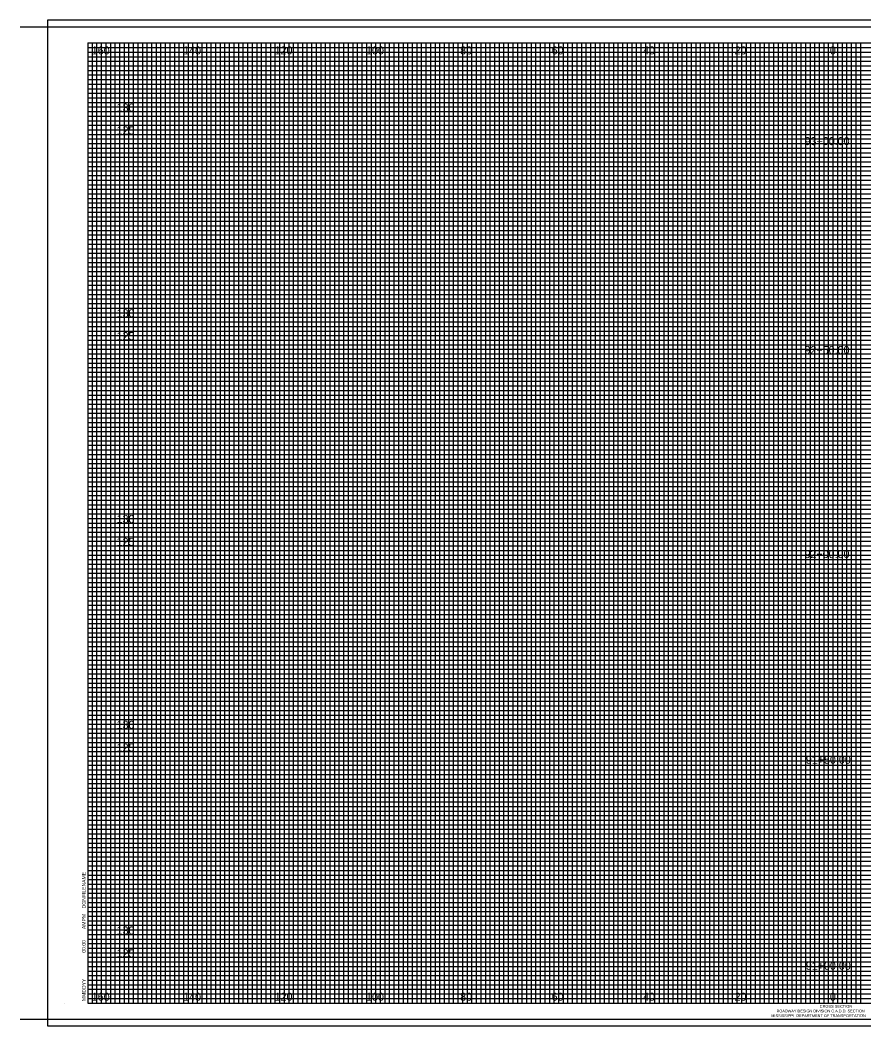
# Model space of a CAD drawing. Extents: x -3604 to 2303, y -13 to 9543.
# Drawn here: x -3604.5 to -3420, y 5764.1 to 5984.1 of the extents above; entities that cross this region are included whole.
import ezdxf

# ---------------------------------------------------------------- set-up
doc = ezdxf.new("R2010")
doc.units = 0
for name, color, linetype in [('SHEET_BORDER', 7, 'Continuous'), ('SHEET_BORDER_TX', 7, 'Continuous'), ('SHEET_DATE_DGN_TX', 7, 'Continuous'), ('SHEET_PLOTTING_SHAPE', 7, 'Continuous'), ('XS_SHEET_LABELS_ELEVATION', 7, 'Continuous'), ('XS_SHEET_LABELS_OFFSET', 7, 'Continuous'), ('XS_SHEET_LABELS_STATION', 7, 'Continuous'), ('XS_SHEET_MAJOR_GRIDS', 7, 'Continuous'), ('XS_SHEET_MEDIUM_GRIDS', 7, 'Continuous'), ('XS_SHEET_MINOR_GRIDS', 7, 'Continuous')]:
    doc.layers.add(name, color=color, linetype=linetype)

msp = doc.modelspace()

# ---------------------------------------------------------------- linework, layer by layer
at = {"layer": 'SHEET_BORDER'}
for p, q in [((-3604.48, 5982.59), (-3252.48, 5982.59)), ((-3589.68, 5979.09), (-3254.68, 5979.09)), ((-3589.68, 5979.09), (-3589.68, 5769.09)), ((-3445.68, 5769.09), (-3445.68, 5979.09)), ((-3594.68, 5769.09), (-3594.68, 5769.09)), ((-3589.68, 5769.09), (-3254.68, 5769.09)), ((-3604.48, 5765.59), (-3252.48, 5765.59))]:
    msp.add_line(p, q, dxfattribs=at)
at = {"layer": 'SHEET_PLOTTING_SHAPE'}
msp.add_lwpolyline([(-3598.48, 5764.09), (-3252.48, 5764.09), (-3252.48, 5984.09), (-3598.48, 5984.09)], close=True, dxfattribs=at)
at = {"layer": 'XS_SHEET_MAJOR_GRIDS'}
for p, q in [((-3584.68, 5769.09), (-3584.68, 5979.09)), ((-3574.68, 5769.09), (-3574.68, 5979.09)), ((-3564.68, 5769.09), (-3564.68, 5979.09)), ((-3554.68, 5769.09), (-3554.68, 5979.09)), ((-3544.68, 5769.09), (-3544.68, 5979.09)), ((-3534.68, 5769.09), (-3534.68, 5979.09)), ((-3524.68, 5769.09), (-3524.68, 5979.09)), ((-3514.68, 5769.09), (-3514.68, 5979.09)), ((-3504.68, 5769.09), (-3504.68, 5979.09)), ((-3494.68, 5769.09), (-3494.68, 5979.09)), ((-3484.68, 5769.09), (-3484.68, 5979.09)), ((-3474.68, 5769.09), (-3474.68, 5979.09)), ((-3464.68, 5769.09), (-3464.68, 5979.09)), ((-3454.68, 5769.09), (-3454.68, 5979.09)), ((-3444.68, 5769.09), (-3444.68, 5979.09)), ((-3434.68, 5769.09), (-3434.68, 5979.09)), ((-3424.68, 5769.09), (-3424.68, 5979.09)), ((-3589.68, 5969.09), (-3254.68, 5969.09)), ((-3589.68, 5959.09), (-3254.68, 5959.09)), ((-3589.68, 5949.09), (-3254.68, 5949.09)), ((-3589.68, 5939.09), (-3254.68, 5939.09)), ((-3589.68, 5929.09), (-3254.68, 5929.09)), ((-3589.68, 5919.09), (-3254.68, 5919.09)), ((-3589.68, 5909.09), (-3254.68, 5909.09)), ((-3589.68, 5899.09), (-3254.68, 5899.09)), ((-3589.68, 5889.09), (-3254.68, 5889.09)), ((-3589.68, 5879.09), (-3254.68, 5879.09)), ((-3589.68, 5869.09), (-3254.68, 5869.09)), ((-3589.68, 5859.09), (-3254.68, 5859.09)), ((-3589.68, 5849.09), (-3254.68, 5849.09)), ((-3589.68, 5839.09), (-3254.68, 5839.09)), ((-3589.68, 5829.09), (-3254.68, 5829.09)), ((-3589.68, 5819.09), (-3254.68, 5819.09)), ((-3589.68, 5809.09), (-3254.68, 5809.09)), ((-3589.68, 5799.09), (-3254.68, 5799.09)), ((-3589.68, 5789.09), (-3254.68, 5789.09)), ((-3589.68, 5779.09), (-3254.68, 5779.09))]:
    msp.add_line(p, q, dxfattribs=at)
at = {"layer": 'XS_SHEET_MEDIUM_GRIDS'}
for p, q in [((-3579.68, 5769.09), (-3579.68, 5979.09)), ((-3569.68, 5769.09), (-3569.68, 5979.09)), ((-3559.68, 5769.09), (-3559.68, 5979.09)), ((-3549.68, 5769.09), (-3549.68, 5979.09)), ((-3539.68, 5769.09), (-3539.68, 5979.09)), ((-3529.68, 5769.09), (-3529.68, 5979.09)), ((-3519.68, 5769.09), (-3519.68, 5979.09)), ((-3509.68, 5769.09), (-3509.68, 5979.09)), ((-3499.68, 5769.09), (-3499.68, 5979.09)), ((-3489.68, 5769.09), (-3489.68, 5979.09)), ((-3479.68, 5769.09), (-3479.68, 5979.09)), ((-3469.68, 5769.09), (-3469.68, 5979.09)), ((-3459.68, 5769.09), (-3459.68, 5979.09)), ((-3449.68, 5769.09), (-3449.68, 5979.09)), ((-3439.68, 5769.09), (-3439.68, 5979.09)), ((-3429.68, 5769.09), (-3429.68, 5979.09)), ((-3589.68, 5974.09), (-3281.68, 5974.09)), ((-3589.68, 5964.09), (-3254.68, 5964.09)), ((-3589.68, 5954.09), (-3254.68, 5954.09)), ((-3589.68, 5944.09), (-3254.68, 5944.09)), ((-3589.68, 5934.09), (-3254.68, 5934.09)), ((-3589.68, 5924.09), (-3254.68, 5924.09)), ((-3589.68, 5914.09), (-3254.68, 5914.09)), ((-3589.68, 5904.09), (-3254.68, 5904.09)), ((-3589.68, 5894.09), (-3254.68, 5894.09)), ((-3589.68, 5884.09), (-3254.68, 5884.09)), ((-3589.68, 5874.09), (-3254.68, 5874.09)), ((-3589.68, 5864.09), (-3254.68, 5864.09)), ((-3589.68, 5854.09), (-3254.68, 5854.09)), ((-3589.68, 5844.09), (-3254.68, 5844.09)), ((-3589.68, 5834.09), (-3254.68, 5834.09)), ((-3589.68, 5824.09), (-3254.68, 5824.09)), ((-3589.68, 5814.09), (-3254.68, 5814.09)), ((-3589.68, 5804.09), (-3254.68, 5804.09)), ((-3589.68, 5794.09), (-3254.68, 5794.09)), ((-3589.68, 5784.09), (-3254.68, 5784.09)), ((-3589.68, 5774.09), (-3264.68, 5774.09))]:
    msp.add_line(p, q, dxfattribs=at)
at = {"layer": 'XS_SHEET_MINOR_GRIDS'}
for p, q in [((-3589.68, 5978.09), (-3281.68, 5978.09)), ((-3588.68, 5769.09), (-3588.68, 5979.09)), ((-3587.68, 5769.09), (-3587.68, 5979.09)), ((-3586.68, 5769.09), (-3586.68, 5979.09)), ((-3585.68, 5769.09), (-3585.68, 5979.09)), ((-3583.68, 5769.09), (-3583.68, 5979.09)), ((-3582.68, 5769.09), (-3582.68, 5979.09)), ((-3581.68, 5769.09), (-3581.68, 5979.09)), ((-3580.68, 5769.09), (-3580.68, 5979.09)), ((-3578.68, 5769.09), (-3578.68, 5979.09)), ((-3577.68, 5769.09), (-3577.68, 5979.09)), ((-3576.68, 5769.09), (-3576.68, 5979.09)), ((-3575.68, 5769.09), (-3575.68, 5979.09)), ((-3573.68, 5769.09), (-3573.68, 5979.09)), ((-3572.68, 5769.09), (-3572.68, 5979.09)), ((-3571.68, 5769.09), (-3571.68, 5979.09)), ((-3570.68, 5769.09), (-3570.68, 5979.09)), ((-3568.68, 5769.09), (-3568.68, 5979.09)), ((-3567.68, 5769.09), (-3567.68, 5979.09)), ((-3566.68, 5769.09), (-3566.68, 5979.09)), ((-3565.68, 5769.09), (-3565.68, 5979.09)), ((-3563.68, 5769.09), (-3563.68, 5979.09)), ((-3562.68, 5769.09), (-3562.68, 5979.09)), ((-3561.68, 5769.09), (-3561.68, 5979.09)), ((-3560.68, 5769.09), (-3560.68, 5979.09)), ((-3558.68, 5769.09), (-3558.68, 5979.09)), ((-3557.68, 5769.09), (-3557.68, 5979.09)), ((-3556.68, 5769.09), (-3556.68, 5979.09)), ((-3555.68, 5769.09), (-3555.68, 5979.09)), ((-3553.68, 5769.09), (-3553.68, 5979.09)), ((-3552.68, 5769.09), (-3552.68, 5979.09)), ((-3551.68, 5769.09), (-3551.68, 5979.09)), ((-3550.68, 5769.09), (-3550.68, 5979.09)), ((-3548.68, 5769.09), (-3548.68, 5979.09)), ((-3547.68, 5769.09), (-3547.68, 5979.09)), ((-3546.68, 5769.09), (-3546.68, 5979.09)), ((-3545.68, 5769.09), (-3545.68, 5979.09)), ((-3543.68, 5769.09), (-3543.68, 5979.09)), ((-3542.68, 5769.09), (-3542.68, 5979.09)), ((-3541.68, 5769.09), (-3541.68, 5979.09)), ((-3540.68, 5769.09), (-3540.68, 5979.09)), ((-3538.68, 5769.09), (-3538.68, 5979.09)), ((-3537.68, 5769.09), (-3537.68, 5979.09)), ((-3536.68, 5769.09), (-3536.68, 5979.09)), ((-3535.68, 5769.09), (-3535.68, 5979.09)), ((-3533.68, 5769.09), (-3533.68, 5979.09)), ((-3532.68, 5769.09), (-3532.68, 5979.09)), ((-3531.68, 5769.09), (-3531.68, 5979.09)), ((-3530.68, 5769.09), (-3530.68, 5979.09)), ((-3528.68, 5769.09), (-3528.68, 5979.09)), ((-3527.68, 5769.09), (-3527.68, 5979.09)), ((-3526.68, 5769.09), (-3526.68, 5979.09)), ((-3525.68, 5769.09), (-3525.68, 5979.09)), ((-3523.68, 5769.09), (-3523.68, 5979.09)), ((-3522.68, 5769.09), (-3522.68, 5979.09)), ((-3521.68, 5769.09), (-3521.68, 5979.09)), ((-3520.68, 5769.09), (-3520.68, 5979.09)), ((-3518.68, 5769.09), (-3518.68, 5979.09)), ((-3517.68, 5769.09), (-3517.68, 5979.09)), ((-3516.68, 5769.09), (-3516.68, 5979.09)), ((-3515.68, 5769.09), (-3515.68, 5979.09)), ((-3513.68, 5769.09), (-3513.68, 5979.09)), ((-3512.68, 5769.09), (-3512.68, 5979.09)), ((-3511.68, 5769.09), (-3511.68, 5979.09)), ((-3510.68, 5769.09), (-3510.68, 5979.09)), ((-3508.68, 5769.09), (-3508.68, 5979.09)), ((-3507.68, 5769.09), (-3507.68, 5979.09)), ((-3506.68, 5769.09), (-3506.68, 5979.09)), ((-3505.68, 5769.09), (-3505.68, 5979.09)), ((-3503.68, 5769.09), (-3503.68, 5979.09)), ((-3502.68, 5769.09), (-3502.68, 5979.09)), ((-3501.68, 5769.09), (-3501.68, 5979.09)), ((-3500.68, 5769.09), (-3500.68, 5979.09)), ((-3498.68, 5769.09), (-3498.68, 5979.09)), ((-3497.68, 5769.09), (-3497.68, 5979.09)), ((-3496.68, 5769.09), (-3496.68, 5979.09)), ((-3495.68, 5769.09), (-3495.68, 5979.09)), ((-3493.68, 5769.09), (-3493.68, 5979.09)), ((-3492.68, 5769.09), (-3492.68, 5979.09)), ((-3491.68, 5769.09), (-3491.68, 5979.09)), ((-3490.68, 5769.09), (-3490.68, 5979.09)), ((-3488.68, 5769.09), (-3488.68, 5979.09)), ((-3487.68, 5769.09), (-3487.68, 5979.09)), ((-3486.68, 5769.09), (-3486.68, 5979.09)), ((-3485.68, 5769.09), (-3485.68, 5979.09)), ((-3483.68, 5769.09), (-3483.68, 5979.09)), ((-3482.68, 5769.09), (-3482.68, 5979.09)), ((-3481.68, 5769.09), (-3481.68, 5979.09)), ((-3480.68, 5769.09), (-3480.68, 5979.09)), ((-3478.68, 5769.09), (-3478.68, 5979.09)), ((-3477.68, 5769.09), (-3477.68, 5979.09)), ((-3476.68, 5769.09), (-3476.68, 5979.09)), ((-3475.68, 5769.09), (-3475.68, 5979.09)), ((-3473.68, 5769.09), (-3473.68, 5979.09)), ((-3472.68, 5769.09), (-3472.68, 5979.09)), ((-3471.68, 5769.09), (-3471.68, 5979.09)), ((-3470.68, 5769.09), (-3470.68, 5979.09)), ((-3468.68, 5769.09), (-3468.68, 5979.09)), ((-3467.68, 5769.09), (-3467.68, 5979.09)), ((-3466.68, 5769.09), (-3466.68, 5979.09)), ((-3465.68, 5769.09), (-3465.68, 5979.09)), ((-3463.68, 5769.09), (-3463.68, 5979.09)), ((-3462.68, 5769.09), (-3462.68, 5979.09)), ((-3461.68, 5769.09), (-3461.68, 5979.09)), ((-3460.68, 5769.09), (-3460.68, 5979.09)), ((-3458.68, 5769.09), (-3458.68, 5979.09)), ((-3457.68, 5769.09), (-3457.68, 5979.09)), ((-3456.68, 5769.09), (-3456.68, 5979.09)), ((-3455.68, 5769.09), (-3455.68, 5979.09)), ((-3453.68, 5769.09), (-3453.68, 5979.09)), ((-3452.68, 5769.09), (-3452.68, 5979.09)), ((-3451.68, 5769.09), (-3451.68, 5979.09)), ((-3450.68, 5769.09), (-3450.68, 5979.09)), ((-3448.68, 5769.09), (-3448.68, 5979.09)), ((-3447.68, 5769.09), (-3447.68, 5979.09)), ((-3446.68, 5769.09), (-3446.68, 5979.09)), ((-3443.68, 5769.09), (-3443.68, 5979.09)), ((-3442.68, 5769.09), (-3442.68, 5979.09)), ((-3441.68, 5769.09), (-3441.68, 5979.09)), ((-3440.68, 5769.09), (-3440.68, 5979.09)), ((-3438.68, 5769.09), (-3438.68, 5979.09)), ((-3437.68, 5769.09), (-3437.68, 5979.09)), ((-3436.68, 5769.09), (-3436.68, 5979.09)), ((-3435.68, 5769.09), (-3435.68, 5979.09)), ((-3433.68, 5769.09), (-3433.68, 5979.09)), ((-3432.68, 5769.09), (-3432.68, 5979.09)), ((-3431.68, 5769.09), (-3431.68, 5979.09)), ((-3430.68, 5769.09), (-3430.68, 5979.09)), ((-3428.68, 5769.09), (-3428.68, 5979.09)), ((-3427.68, 5769.09), (-3427.68, 5979.09)), ((-3426.68, 5769.09), (-3426.68, 5979.09)), ((-3425.68, 5769.09), (-3425.68, 5979.09)), ((-3423.68, 5769.09), (-3423.68, 5979.09)), ((-3422.68, 5769.09), (-3422.68, 5979.09)), ((-3421.68, 5769.09), (-3421.68, 5979.09)), ((-3420.68, 5769.09), (-3420.68, 5979.09)), ((-3589.68, 5977.09), (-3281.68, 5977.09)), ((-3589.68, 5976.09), (-3281.68, 5976.09)), ((-3589.68, 5975.09), (-3281.68, 5975.09)), ((-3589.68, 5973.09), (-3281.68, 5973.09)), ((-3589.68, 5972.09), (-3281.68, 5972.09)), ((-3589.68, 5971.09), (-3281.68, 5971.09)), ((-3589.68, 5970.09), (-3254.68, 5970.09)), ((-3589.68, 5968.09), (-3254.68, 5968.09)), ((-3589.68, 5967.09), (-3254.68, 5967.09)), ((-3589.68, 5966.09), (-3254.68, 5966.09)), ((-3589.68, 5965.09), (-3254.68, 5965.09)), ((-3589.68, 5963.09), (-3254.68, 5963.09)), ((-3589.68, 5962.09), (-3254.68, 5962.09)), ((-3589.68, 5961.09), (-3254.68, 5961.09)), ((-3589.68, 5960.09), (-3254.68, 5960.09)), ((-3589.68, 5958.09), (-3254.68, 5958.09)), ((-3589.68, 5957.09), (-3254.68, 5957.09)), ((-3589.68, 5956.09), (-3254.68, 5956.09)), ((-3589.68, 5955.09), (-3254.68, 5955.09)), ((-3589.68, 5953.09), (-3254.68, 5953.09)), ((-3589.68, 5952.09), (-3254.68, 5952.09)), ((-3589.68, 5951.09), (-3254.68, 5951.09)), ((-3589.68, 5950.09), (-3254.68, 5950.09)), ((-3589.68, 5948.09), (-3254.68, 5948.09)), ((-3589.68, 5947.09), (-3254.68, 5947.09)), ((-3589.68, 5946.09), (-3254.68, 5946.09)), ((-3589.68, 5945.09), (-3254.68, 5945.09)), ((-3589.68, 5943.09), (-3254.68, 5943.09)), ((-3589.68, 5942.09), (-3254.68, 5942.09)), ((-3589.68, 5941.09), (-3254.68, 5941.09)), ((-3589.68, 5940.09), (-3254.68, 5940.09)), ((-3589.68, 5938.09), (-3254.68, 5938.09)), ((-3589.68, 5937.09), (-3254.68, 5937.09)), ((-3589.68, 5936.09), (-3254.68, 5936.09)), ((-3589.68, 5935.09), (-3254.68, 5935.09)), ((-3589.68, 5933.09), (-3254.68, 5933.09)), ((-3589.68, 5932.09), (-3254.68, 5932.09)), ((-3589.68, 5931.09), (-3254.68, 5931.09)), ((-3589.68, 5930.09), (-3254.68, 5930.09)), ((-3589.68, 5928.09), (-3254.68, 5928.09)), ((-3589.68, 5927.09), (-3254.68, 5927.09)), ((-3589.68, 5926.09), (-3254.68, 5926.09)), ((-3589.68, 5925.09), (-3254.68, 5925.09)), ((-3589.68, 5923.09), (-3254.68, 5923.09)), ((-3589.68, 5922.09), (-3254.68, 5922.09)), ((-3589.68, 5921.09), (-3254.68, 5921.09)), ((-3589.68, 5920.09), (-3254.68, 5920.09)), ((-3589.68, 5918.09), (-3254.68, 5918.09)), ((-3589.68, 5917.09), (-3254.68, 5917.09)), ((-3589.68, 5916.09), (-3254.68, 5916.09)), ((-3589.68, 5915.09), (-3254.68, 5915.09)), ((-3589.68, 5913.09), (-3254.68, 5913.09)), ((-3589.68, 5912.09), (-3254.68, 5912.09)), ((-3589.68, 5911.09), (-3254.68, 5911.09)), ((-3589.68, 5910.09), (-3254.68, 5910.09)), ((-3589.68, 5908.09), (-3254.68, 5908.09)), ((-3589.68, 5907.09), (-3254.68, 5907.09)), ((-3589.68, 5906.09), (-3254.68, 5906.09)), ((-3589.68, 5905.09), (-3254.68, 5905.09)), ((-3589.68, 5903.09), (-3254.68, 5903.09)), ((-3589.68, 5902.09), (-3254.68, 5902.09)), ((-3589.68, 5901.09), (-3254.68, 5901.09)), ((-3589.68, 5900.09), (-3254.68, 5900.09)), ((-3589.68, 5898.09), (-3254.68, 5898.09)), ((-3589.68, 5897.09), (-3254.68, 5897.09)), ((-3589.68, 5896.09), (-3254.68, 5896.09)), ((-3589.68, 5895.09), (-3254.68, 5895.09)), ((-3589.68, 5893.09), (-3254.68, 5893.09)), ((-3589.68, 5892.09), (-3254.68, 5892.09)), ((-3589.68, 5891.09), (-3254.68, 5891.09)), ((-3589.68, 5890.09), (-3254.68, 5890.09)), ((-3589.68, 5888.09), (-3254.68, 5888.09)), ((-3589.68, 5887.09), (-3254.68, 5887.09)), ((-3589.68, 5886.09), (-3254.68, 5886.09)), ((-3589.68, 5885.09), (-3254.68, 5885.09)), ((-3589.68, 5883.09), (-3254.68, 5883.09)), ((-3589.68, 5882.09), (-3254.68, 5882.09)), ((-3589.68, 5881.09), (-3254.68, 5881.09)), ((-3589.68, 5880.09), (-3254.68, 5880.09)), ((-3589.68, 5878.09), (-3254.68, 5878.09)), ((-3589.68, 5877.09), (-3254.68, 5877.09)), ((-3589.68, 5876.09), (-3254.68, 5876.09)), ((-3589.68, 5875.09), (-3254.68, 5875.09)), ((-3589.68, 5873.09), (-3254.68, 5873.09)), ((-3589.68, 5872.09), (-3254.68, 5872.09)), ((-3589.68, 5871.09), (-3254.68, 5871.09)), ((-3589.68, 5870.09), (-3254.68, 5870.09)), ((-3589.68, 5868.09), (-3254.68, 5868.09)), ((-3589.68, 5867.09), (-3254.68, 5867.09)), ((-3589.68, 5866.09), (-3254.68, 5866.09)), ((-3589.68, 5865.09), (-3254.68, 5865.09)), ((-3589.68, 5863.09), (-3254.68, 5863.09)), ((-3589.68, 5862.09), (-3254.68, 5862.09)), ((-3589.68, 5861.09), (-3254.68, 5861.09)), ((-3589.68, 5860.09), (-3254.68, 5860.09)), ((-3589.68, 5858.09), (-3254.68, 5858.09)), ((-3589.68, 5857.09), (-3254.68, 5857.09)), ((-3589.68, 5856.09), (-3254.68, 5856.09)), ((-3589.68, 5855.09), (-3254.68, 5855.09)), ((-3589.68, 5853.09), (-3254.68, 5853.09)), ((-3589.68, 5852.09), (-3254.68, 5852.09)), ((-3589.68, 5851.09), (-3254.68, 5851.09)), ((-3589.68, 5850.09), (-3254.68, 5850.09)), ((-3589.68, 5848.09), (-3254.68, 5848.09)), ((-3589.68, 5847.09), (-3254.68, 5847.09)), ((-3589.68, 5846.09), (-3254.68, 5846.09)), ((-3589.68, 5845.09), (-3254.68, 5845.09)), ((-3589.68, 5843.09), (-3254.68, 5843.09)), ((-3589.68, 5842.09), (-3254.68, 5842.09)), ((-3589.68, 5841.09), (-3254.68, 5841.09)), ((-3589.68, 5840.09), (-3254.68, 5840.09)), ((-3589.68, 5838.09), (-3254.68, 5838.09)), ((-3589.68, 5837.09), (-3254.68, 5837.09)), ((-3589.68, 5836.09), (-3254.68, 5836.09)), ((-3589.68, 5835.09), (-3254.68, 5835.09)), ((-3589.68, 5833.09), (-3254.68, 5833.09)), ((-3589.68, 5832.09), (-3254.68, 5832.09)), ((-3589.68, 5831.09), (-3254.68, 5831.09)), ((-3589.68, 5830.09), (-3254.68, 5830.09)), ((-3589.68, 5828.09), (-3254.68, 5828.09)), ((-3589.68, 5827.09), (-3254.68, 5827.09)), ((-3589.68, 5826.09), (-3254.68, 5826.09)), ((-3589.68, 5825.09), (-3254.68, 5825.09)), ((-3589.68, 5823.09), (-3254.68, 5823.09)), ((-3589.68, 5822.09), (-3254.68, 5822.09)), ((-3589.68, 5821.09), (-3254.68, 5821.09)), ((-3589.68, 5820.09), (-3254.68, 5820.09)), ((-3589.68, 5818.09), (-3254.68, 5818.09)), ((-3589.68, 5817.09), (-3254.68, 5817.09)), ((-3589.68, 5816.09), (-3254.68, 5816.09)), ((-3589.68, 5815.09), (-3254.68, 5815.09)), ((-3589.68, 5813.09), (-3254.68, 5813.09)), ((-3589.68, 5812.09), (-3254.68, 5812.09)), ((-3589.68, 5811.09), (-3254.68, 5811.09)), ((-3589.68, 5810.09), (-3254.68, 5810.09)), ((-3589.68, 5808.09), (-3254.68, 5808.09)), ((-3589.68, 5807.09), (-3254.68, 5807.09)), ((-3589.68, 5806.09), (-3254.68, 5806.09)), ((-3589.68, 5805.09), (-3254.68, 5805.09)), ((-3589.68, 5803.09), (-3254.68, 5803.09)), ((-3589.68, 5802.09), (-3254.68, 5802.09)), ((-3589.68, 5801.09), (-3254.68, 5801.09)), ((-3589.68, 5800.09), (-3254.68, 5800.09)), ((-3589.68, 5798.09), (-3254.68, 5798.09)), ((-3589.68, 5797.09), (-3254.68, 5797.09)), ((-3589.68, 5796.09), (-3254.68, 5796.09)), ((-3589.68, 5795.09), (-3254.68, 5795.09)), ((-3589.68, 5793.09), (-3254.68, 5793.09)), ((-3589.68, 5792.09), (-3254.68, 5792.09)), ((-3589.68, 5791.09), (-3254.68, 5791.09)), ((-3589.68, 5790.09), (-3254.68, 5790.09)), ((-3589.68, 5790.09), (-3254.68, 5790.09)), ((-3589.68, 5790.09), (-3254.68, 5790.09)), ((-3589.68, 5788.09), (-3254.68, 5788.09)), ((-3589.68, 5787.09), (-3254.68, 5787.09)), ((-3589.68, 5786.09), (-3254.68, 5786.09)), ((-3589.68, 5785.09), (-3254.68, 5785.09)), ((-3589.68, 5783.09), (-3254.68, 5783.09)), ((-3589.68, 5782.09), (-3254.68, 5782.09)), ((-3589.68, 5781.09), (-3254.68, 5781.09)), ((-3589.68, 5780.09), (-3254.68, 5780.09)), ((-3589.68, 5778.09), (-3264.68, 5778.09)), ((-3589.68, 5777.09), (-3264.68, 5777.09)), ((-3589.68, 5776.09), (-3264.68, 5776.09)), ((-3589.68, 5775.09), (-3264.68, 5775.09)), ((-3589.68, 5775.09), (-3264.68, 5775.09)), ((-3589.68, 5775.09), (-3264.68, 5775.09)), ((-3589.68, 5773.09), (-3264.68, 5773.09)), ((-3589.68, 5772.09), (-3264.68, 5772.09)), ((-3589.68, 5771.09), (-3264.68, 5771.09)), ((-3589.68, 5770.09), (-3264.68, 5770.09))]:
    msp.add_line(p, q, dxfattribs=at)

# ---------------------------------------------------------------- texts
at = {"layer": 'SHEET_BORDER_TX'}
for s, height, p in [('CROSS SECTION', 0.62, (-3429.64, 5768.06)), ('MISSISSIPPI  DEPARTMENT OF TRANSPORTATION', 0.61, (-3440.24, 5766.01)), ('ROADWAY DESIGN DIVISION C.A.D.D. SECTION', 0.61, (-3439.08, 5767.04))]:
    msp.add_text(s, height=height, dxfattribs=at).set_placement(p)
at = {"layer": 'SHEET_DATE_DGN_TX'}
for s, p in [('DGNFILENAME', (-3590.15, 5789.79)), ('AMPM', (-3590.15, 5785.27)), ('00:00', (-3590.15, 5780.09)), ('MMDDYY', (-3590.15, 5769.51))]:
    msp.add_text(s, height=0.8, rotation=90, dxfattribs=at).set_placement(p)
at = {"layer": 'XS_SHEET_LABELS_ELEVATION'}
for s, p in [('  130  ', (-3584.68, 5964.09)), ('  125  ', (-3584.68, 5959.09)), ('  130  ', (-3584.68, 5919.09)), ('  125  ', (-3584.68, 5914.09)), ('  130  ', (-3584.68, 5874.09)), ('  125  ', (-3584.68, 5869.09)), ('  130  ', (-3584.68, 5829.09)), ('  125  ', (-3584.68, 5824.09)), ('  130  ', (-3584.68, 5784.09)), ('  125  ', (-3584.68, 5779.09))]:
    msp.add_text(s, height=1.75, dxfattribs=at).set_placement(p)
at = {"layer": 'XS_SHEET_LABELS_OFFSET'}
for s, p in [('  160  ', (-3590.11, 5976.59)), ('  140  ', (-3570.13, 5976.59)), ('  120  ', (-3550.13, 5976.59)), ('  100  ', (-3530.13, 5976.59)), ('  80  ', (-3509.56, 5976.59)), ('  60  ', (-3489.55, 5976.59)), ('  40  ', (-3469.56, 5976.59)), ('  20  ', (-3449.56, 5976.59)), ('  0  ', (-3428.71, 5976.59)), ('  0  ', (-3428.71, 5976.59)), ('  160  ', (-3590.11, 5769.59)), ('  140  ', (-3570.13, 5769.59)), ('  120  ', (-3550.13, 5769.59)), ('  100  ', (-3530.13, 5769.59)), ('  80  ', (-3509.56, 5769.59)), ('  60  ', (-3489.55, 5769.59)), ('  40  ', (-3469.56, 5769.59)), ('  20  ', (-3449.56, 5769.59)), ('  0  ', (-3428.71, 5769.59)), ('  0  ', (-3428.71, 5769.59))]:
    msp.add_text(s, height=1.75, dxfattribs=at).set_placement(p)
at = {"layer": 'XS_SHEET_LABELS_STATION'}
for s, p in [('  93+00.00  ', (-3434.23, 5956.75)), ('  92+50.00  ', (-3434.26, 5911.05)), ('  92+00.00  ', (-3434.26, 5866.42)), ('  91+50.00  ', (-3433.97, 5821.43)), ('  91+00.00  ', (-3433.97, 5776.37))]:
    msp.add_text(s, height=1.75, dxfattribs=at).set_placement(p)

doc.saveas('drawing.dxf')
